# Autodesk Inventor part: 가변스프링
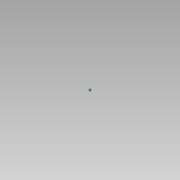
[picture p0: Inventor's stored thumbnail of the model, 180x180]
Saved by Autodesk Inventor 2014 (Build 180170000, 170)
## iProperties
Created: 2015-04
Part Number: 가변스프링
Material: Generic
Document SubType Name: Modeling
Designer: Administrator
Density: 1 g/cm^3
Appearance: Default
Mass: 0.60807 g
Surface Area: 12.5277 cm^2
Volume: 0.60807 cm^3
Author: Administrator
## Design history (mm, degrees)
sketch "스케치1"
  geometry: L1 (0, 11.5)-(8, 11.5); L2 (8, 11.5)-(8, 0); L3 (8, 0)-(0, 0); L4 (0, 0)-(0, 11.5); C1 r 1 at (8, 0); 1 further point
  constraints: 8 end point, 2 coincident, 2 parallel, 1 centre point, 1 horizontal, 1 perpendicular
  dimensions: "d0" = 16 diameter of L2 L4; "d1" = 11.50049 distance between parallel lines of L3 L1 (derived); "d2" = 2 diameter of C1
feature "코일1" pitch "d3" = 10; turns "d5" = 4; dims "d4" = 11.50049 (= d1), "d6" = 0, angle "d7" = 90 deg, angle "d8" = 90 deg, "d9" = 0, "d10" = 0
sketch "스케치2"
  geometry: L1 (-9, 0)-(-7, 0) reference; 1 further point
  constraints: 1 horizontal alignment
extrude "돌출1" cut sketch "스케치2" stored distance "d11" = 10; taper "d12" = 0 deg
node "작업 평면1"
sketch "스케치3"
  geometry: L1 (9, 0)-(7, 0) reference; 1 further point
  constraints: 1 horizontal alignment
extrude "돌출2" cut sketch "스케치3" stored distance "d13" = 10; taper "d14" = 0 deg
node "솔리드1"
node "절단 모서리 투영1"
node "절단 모서리 투영2"
